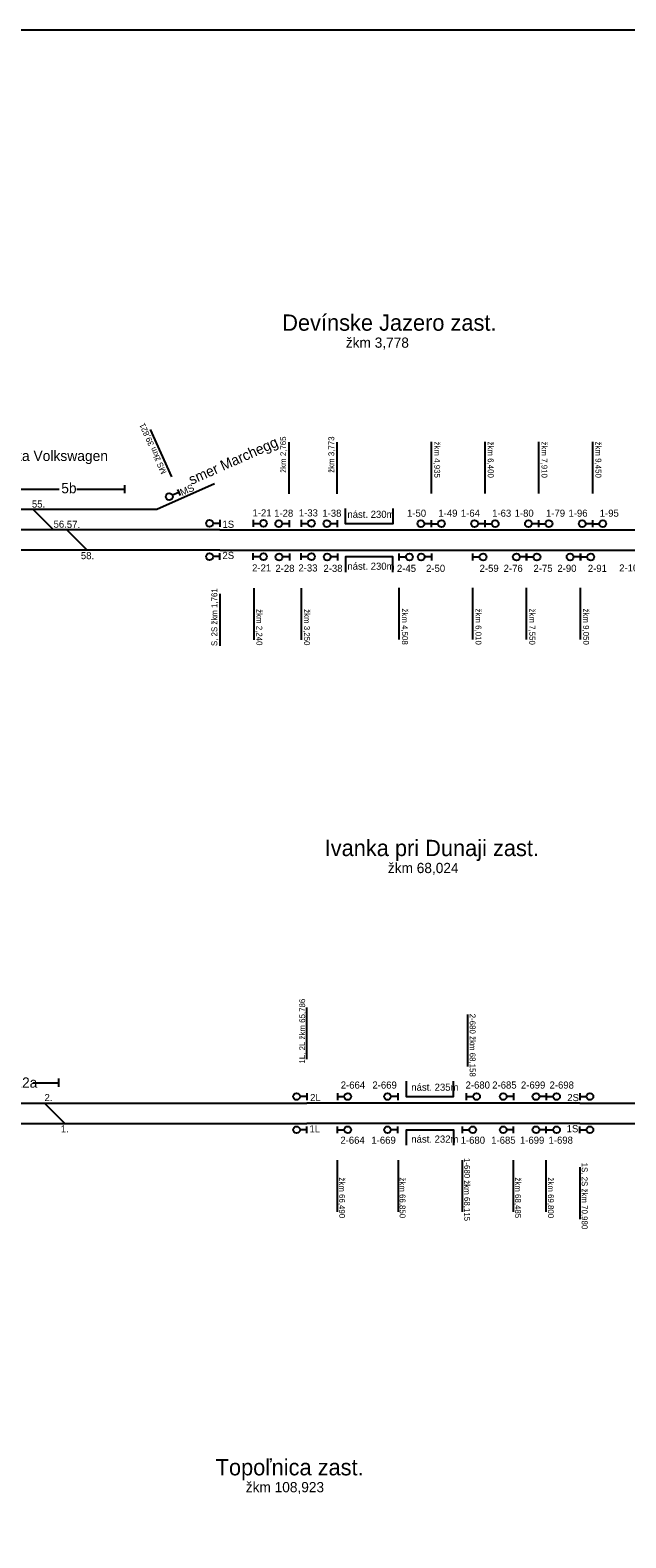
# Model space of a CAD drawing. Extents: x -119 to 851, y -238 to 59.
# Drawn here: x -6.1 to 52.5, y -89.2 to 59 of the extents above; entities that cross this region are included whole.
import ezdxf

# ---------------------------------------------------------------- set-up
doc = ezdxf.new("R2010")
doc.units = 0
for name, color, linetype in [('Level 2', 7, 'Continuous'), ('nastupistia', 7, 'Continuous'), ('netlač', 7, 'Continuous'), ('popisky navestidla', 7, 'Continuous'), ('popisky stanic a zastavok', 7, 'Continuous'), ('PU_navestidla', 7, 'Continuous'), ('PU_oznacenie navestidiel', 7, 'Continuous'), ('PU_stan_kolaje', 7, 'Continuous'), ('PU_vlecky', 7, 'Continuous')]:
    doc.layers.add(name, color=color, linetype=linetype)

msp = doc.modelspace()

# ---------------------------------------------------------------- linework, layer by layer
at = {"layer": 'Level 2'}
for p, q in [((3.22, 14.29), (3.22, 13.49)), ((12.58, 9.89), (-11.45, 9.89)), ((3.55, 7.89), (-12.65, 7.89)), ((12.58, 7.89), (3.55, 7.89)), ((-5.79, -44.45), (-3.26, -44.45)), ((-3.26, -44.85), (-3.26, -44.05)), ((-8.59, -46.45), (-1.55, -46.45)), ((-1.55, -46.45), (21.12, -46.45)), ((47.92, -46.45), (53.83, -46.45)), ((-9.31, -48.45), (-0.55, -48.45)), ((-0.55, -48.45), (17.74, -48.45)), ((17.74, -48.45), (21.12, -48.45)), ((47.92, -48.45), (68.83, -48.45))]:
    msp.add_line(p, q, dxfattribs=at)
at = {"layer": 'nastupistia'}
for points in [[(29.55, 11.99), (29.55, 10.49), (24.91, 10.49), (24.91, 11.99)], [(29.55, 5.72), (29.55, 7.22), (24.91, 7.22), (24.91, 5.72)], [(30.89, -44.31), (30.89, -45.81), (35.53, -45.81), (35.53, -44.31)], [(30.9, -50.59), (30.9, -49.08), (35.53, -49.08), (35.53, -50.59)]]:
    msp.add_lwpolyline(points, dxfattribs=at)
at = {"layer": 'netlač'}
for p, q in [((-9.88, 13.89), (-3.21, 13.89)), ((-1.48, 13.89), (3.22, 13.89)), ((12.04, 14.42), (6.37, 11.89)), ((6.37, 11.89), (-34.5, 11.89)), ((12.58, 9.89), (61.62, 9.89)), ((12.58, 7.89), (61.62, 7.89)), ((47.92, -46.45), (21.12, -46.45)), ((47.92, -48.45), (21.12, -48.45))]:
    msp.add_line(p, q, dxfattribs=at)
at = {"layer": 'popisky navestidla'}
for p, q in [((7.85, 15.08), (5.77, 19.73)), ((19.35, 18.5), (19.35, 13.41)), ((24.07, 18.5), (24.07, 13.41)), ((33.37, 13.45), (33.37, 18.54)), ((38.63, 13.45), (38.63, 18.54)), ((43.91, 13.45), (43.91, 18.54)), ((49.21, 13.45), (49.21, 18.54)), ((12.58, 3.58), (12.58, -1.51)), ((15.91, 4.15), (15.91, -0.94)), ((20.57, 4.15), (20.57, -0.94)), ((30.2, -0.89), (30.2, 4.2)), ((37.43, -0.89), (37.43, 4.2)), ((42.71, -0.89), (42.71, 4.2)), ((48, -0.89), (48, 4.2)), ((21.12, -42.14), (21.12, -37.05)), ((36.92, -42.85), (36.92, -37.76)), ((24.09, -52.05), (24.09, -57.14)), ((30.08, -52.05), (30.08, -57.14)), ((36.37, -52.05), (36.37, -57.14)), ((41.38, -52.05), (41.38, -57.14)), ((44.61, -52.05), (44.61, -57.14)), ((47.92, -52.76), (47.92, -57.85))]:
    msp.add_line(p, q, dxfattribs=at)
msp.add_lwpolyline([(-118.95, -238.01), (851.05, -238.01), (851.05, 58.99), (-118.95, 58.99)], close=True, dxfattribs=at)
at = {"layer": 'PU_navestidla'}
for p, q in [((8.53, 13.55), (7.92, 13.28)), ((8.4, 13.86), (8.67, 13.25)), ((12.58, 10.52), (11.91, 10.52)), ((12.58, 10.86), (12.58, 10.19)), ((15.86, 10.86), (15.86, 10.19)), ((15.86, 10.52), (16.53, 10.52)), ((19.37, 10.49), (18.69, 10.49)), ((19.37, 10.83), (19.37, 10.15)), ((20.55, 10.86), (20.55, 10.19)), ((20.55, 10.52), (21.23, 10.52)), ((24.09, 10.49), (23.42, 10.49)), ((24.09, 10.83), (24.09, 10.15)), ((33.33, 10.49), (32.65, 10.49)), ((33.33, 10.83), (33.33, 10.15)), ((33.33, 10.83), (33.33, 10.15)), ((33.33, 10.49), (34, 10.49)), ((38.61, 10.49), (37.94, 10.49)), ((38.61, 10.83), (38.61, 10.15)), ((38.61, 10.83), (38.61, 10.15)), ((38.61, 10.49), (39.28, 10.49)), ((43.89, 10.49), (43.22, 10.49)), ((43.89, 10.83), (43.89, 10.15)), ((43.89, 10.83), (43.89, 10.15)), ((43.89, 10.49), (44.57, 10.49)), ((49.18, 10.49), (48.51, 10.49)), ((49.18, 10.83), (49.18, 10.15)), ((49.18, 10.83), (49.18, 10.15)), ((49.18, 10.49), (49.85, 10.49)), ((12.58, 6.92), (12.58, 7.59)), ((15.86, 6.92), (15.86, 7.59)), ((19.4, 7.55), (19.4, 6.88)), ((20.55, 6.92), (20.55, 7.59)), ((24.12, 7.55), (24.12, 6.88)), ((30.19, 6.88), (30.19, 7.55)), ((33.36, 7.55), (33.36, 6.88)), ((37.42, 6.88), (37.42, 7.55)), ((42.71, 6.88), (42.71, 7.55)), ((42.71, 7.55), (42.71, 6.88)), ((47.99, 6.88), (47.99, 7.55)), ((47.99, 7.55), (47.99, 6.88)), ((12.58, 7.25), (11.91, 7.25)), ((15.86, 7.25), (16.53, 7.25)), ((19.4, 7.22), (18.72, 7.22)), ((20.55, 7.25), (21.23, 7.25)), ((24.12, 7.22), (23.45, 7.22)), ((30.19, 7.22), (30.87, 7.22)), ((33.36, 7.22), (32.68, 7.22)), ((37.42, 7.22), (38.09, 7.22)), ((42.71, 7.22), (42.03, 7.22)), ((42.71, 7.22), (43.38, 7.22)), ((47.99, 7.22), (47.32, 7.22)), ((47.99, 7.22), (48.66, 7.22)), ((21.12, -45.81), (20.44, -45.81)), ((21.12, -45.48), (21.12, -46.15)), ((24.13, -45.48), (24.13, -46.15)), ((24.13, -45.81), (24.8, -45.81)), ((30.05, -45.81), (29.38, -45.81)), ((30.05, -45.48), (30.05, -46.15)), ((36.78, -45.48), (36.78, -46.15)), ((36.78, -45.81), (37.45, -45.81)), ((41.41, -45.81), (40.74, -45.81)), ((41.41, -45.48), (41.41, -46.15)), ((44.64, -45.81), (43.97, -45.81)), ((44.64, -45.48), (44.64, -46.15)), ((44.64, -45.48), (44.64, -46.15)), ((44.64, -45.81), (45.31, -45.81)), ((47.92, -45.48), (47.92, -46.15)), ((47.92, -45.81), (48.59, -45.81)), ((21.12, -49.42), (21.12, -48.75)), ((24.13, -49.42), (24.13, -48.75)), ((30.05, -49.42), (30.05, -48.75)), ((36.41, -49.42), (36.41, -48.75)), ((41.41, -49.42), (41.41, -48.75)), ((44.64, -49.42), (44.64, -48.75)), ((44.64, -49.42), (44.64, -48.75)), ((47.92, -49.42), (47.92, -48.75)), ((21.12, -49.08), (20.44, -49.08)), ((24.13, -49.08), (24.8, -49.08)), ((30.05, -49.08), (29.38, -49.08)), ((36.41, -49.08), (37.08, -49.08)), ((41.41, -49.08), (40.74, -49.08)), ((44.64, -49.08), (43.97, -49.08)), ((44.64, -49.08), (45.31, -49.08)), ((47.92, -49.08), (48.59, -49.08))]:
    msp.add_line(p, q, dxfattribs=at)
for centre in [(7.61, 13.14), (11.57, 10.53), (16.86, 10.52), (18.36, 10.49), (21.56, 10.52), (23.09, 10.49), (32.32, 10.49), (34.33, 10.49), (37.6, 10.49), (39.62, 10.49), (42.89, 10.49), (44.9, 10.49), (48.17, 10.49), (50.19, 10.49), (11.57, 7.25), (16.86, 7.25), (18.39, 7.22), (21.56, 7.25), (23.12, 7.22), (31.2, 7.22), (32.35, 7.22), (38.43, 7.22), (41.7, 7.22), (43.72, 7.22), (46.98, 7.22), (49, 7.22), (20.11, -45.81), (25.13, -45.81), (29.04, -45.81), (37.79, -45.81), (40.41, -45.81), (43.63, -45.81), (45.65, -45.81), (48.92, -45.81), (20.11, -49.08), (25.13, -49.08), (29.04, -49.08), (37.42, -49.08), (40.41, -49.08), (43.63, -49.08), (45.65, -49.08), (48.92, -49.08)]:
    msp.add_circle(centre, 0.336, dxfattribs=at)
at = {"layer": 'PU_stan_kolaje'}
for points in [[(-3.77, 9.89), (-5.77, 11.89)], [(-0.45, 7.89), (-2.45, 9.89)], [(-4.66, -46.45), (-2.66, -48.45)]]:
    msp.add_lwpolyline(points, dxfattribs=at)

# ---------------------------------------------------------------- texts
at = {"layer": 'nastupistia'}
for s, p in [('nást. 230m', (25.1, 11.06)), ('nást. 230m', (25.1, 5.96)), ('nást. 235m', (31.38, -45.24)), ('nást. 232m', (31.38, -50.34))]:
    msp.add_text(s, height=0.7, dxfattribs=at).set_placement(p)
at = {"layer": 'popisky navestidla'}
for s, height, rotation, p in [('MS žkm 39,821 ', 0.5793, 114.0712, (7.36, 15.53)), ('žkm 2,765', 0.579, 90, (19.08, 15.49)), ('žkm 3,773', 0.579, 90, (23.81, 15.49)), ('žkm 4,935', 0.579, 270, (33.63, 18.56)), ('žkm 6,400', 0.579, 270, (38.89, 18.56)), ('žkm 7,910', 0.579, 270, (44.17, 18.56)), ('žkm 9,450', 0.579, 270, (49.47, 18.56)), ('S, 2S žkm 1,761', 0.5793, 90, (12.32, -1.54)), ('žkm 2,240', 0.579, 270, (16.17, 2.09)), ('žkm 3,250', 0.579, 270, (20.84, 2.09)), ('žkm 4,508', 0.579, 270, (30.46, 2.16)), ('žkm 6,010', 0.579, 270, (37.69, 2.15)), ('žkm 7,550', 0.579, 270, (42.97, 2.15)), ('žkm 9,050', 0.579, 270, (48.26, 2.15)), ('1L, 2L žkm 65,786', 0.5793, 90, (20.95, -42.57)), ('2-680 žkm 68,158', 0.5793, 270, (37.11, -37.67)), ('1-680 žkm 68,115', 0.5793, 270, (36.57, -51.85)), ('1S, 2S žkm 70,980', 0.5793, 270, (48.12, -52.31)), ('žkm 66,490', 0.579, 270, (24.29, -53.76)), ('žkm 66,850', 0.579, 270, (30.23, -53.76)), ('žkm 68,485', 0.579, 270, (41.57, -53.76)), ('žkm 69,800', 0.579, 270, (44.8, -53.76))]:
    msp.add_text(s, height=height, rotation=rotation, dxfattribs=at).set_placement(p)
at = {"layer": 'popisky stanic a zastavok'}
for s, height, p in [('Devínske Jazero zast.', 1.6, (18.7, 29.45)), ('žkm 3,778', 1.004, (24.95, 27.78)), ('Ivanka pri Dunaji zast.', 1.6, (22.87, -22.18)), ('žkm 68,024', 1.004, (29.08, -23.85)), ('Topoľnica zast.', 1.6, (12.16, -83.04)), ('žkm 108,923', 1.0044, (15.12, -84.7))]:
    msp.add_text(s, height=height, dxfattribs=at).set_placement(p)
at = {"layer": 'PU_oznacenie navestidiel'}
msp.add_text('MS', height=0.7, rotation=24.0712, dxfattribs=at).set_placement((8.85, 13.2))
for s, p in [('55.', (-5.89, 12.07)), ('1-21', (15.78, 11.2)), ('1-28', (17.91, 11.17)), ('1-33', (20.33, 11.2)), ('1-38', (22.64, 11.17)), ('1-50', (30.96, 11.17)), ('1-49', (34.04, 11.17)), ('1-64', (36.25, 11.17)), ('1-63', (39.32, 11.17)), ('1-80', (41.53, 11.17)), ('1-79', (44.61, 11.17)), ('1-96', (46.82, 11.17)), ('1-95', (49.89, 11.17)), ('56.', (-3.76, 10.09)), ('57.', (-2.46, 10.07)), ('1S', (12.83, 10.08)), ('58.', (-1.08, 7)), ('2S', (12.83, 7.02)), ('2-21', (15.74, 5.79)), ('2-28', (18.03, 5.75)), ('2-33', (20.29, 5.79)), ('2-38', (22.75, 5.75)), ('2-45', (29.97, 5.75)), ('2-50', (32.83, 5.75)), ('2-59', (38.09, 5.75)), ('2-76', (40.45, 5.75)), ('2-75', (43.38, 5.75)), ('2-90', (45.73, 5.75)), ('2-91', (48.72, 5.75)), ('2-106', (51.8, 5.79)), ('2-664', (24.45, -45.03)), ('2-669', (27.56, -45.03)), ('2-680', (36.71, -45.03)), ('2-685', (39.33, -45.03)), ('2-699', (42.15, -45.03)), ('2-698', (44.96, -45.03)), ('2.', (-4.65, -46.26)), ('2L', (21.44, -46.26)), ('2S', (46.7, -46.26)), ('1.', (-3.05, -49.33)), ('1L', (21.38, -49.33)), ('1S', (46.64, -49.32)), ('2-664', (24.41, -50.45)), ('1-669', (27.46, -50.45)), ('1-680', (36.23, -50.45)), ('1-685', (39.23, -50.45)), ('1-699', (42.05, -50.45)), ('1-698', (44.86, -50.45))]:
    msp.add_text(s, height=0.7, dxfattribs=at).set_placement(p)
at = {"layer": 'PU_stan_kolaje'}
for s, p in [('5b', (-3, 13.48)), ('12a', (-7.6, -44.94))]:
    msp.add_text(s, height=1.004, dxfattribs=at).set_placement(p)
at = {"layer": 'PU_vlecky'}
msp.add_text('smer Marchegg', height=1.015, rotation=24.0712, dxfattribs=at).set_placement((9.79, 14.29))
msp.add_text('vlečka Volkswagen', height=1.015, dxfattribs=at).set_placement((-9.96, 16.65))

doc.saveas('drawing.dxf')
